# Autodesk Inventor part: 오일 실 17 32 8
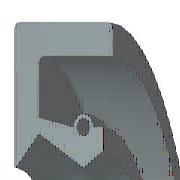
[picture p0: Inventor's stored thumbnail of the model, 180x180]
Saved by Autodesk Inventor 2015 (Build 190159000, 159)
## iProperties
IsCustomPart: 1
Created: 2012-02
Part Number: 오일 실 17 32 8
Material: 고무
Description: 오일-실
Document SubType Name: Modeling
Standard: KS B 2804
Designer: mduedu
Standards Organization: KS
Language: ko-KR
Size Designation: D - 17 32 8
Categories: <MemberInstance><Categories><Category DisplayName="샤프트 부품" InternalName="7f7aeb1f-a693-4053-b835-cee3144e0d98" Mnemonic="SHFT"><Category DisplayName="실링" Intern
Density: 0.93 g/cm^3
Appearance: 고무 - 검은색 - 버전 1.1
Author: mduedu
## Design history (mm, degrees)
revolve "본체" stored, may be unused: angle "d17" = 90 deg
revolve "스프링1" stored, may be unused: angle "d18" = 90 deg
body "Solid1"
sketch "스케치1"
  geometry: L1 (0, 16)-(8, 16); L2 (8, 14.25)-(1.75, 14.25); L3 (1.75, 10.25)-(4.9, 8.5); L4 (4.9, 8.5)-(0, 8.5); L5 (0, 0)-(9.586, 0) reference; L6 (4.9, 8.5)-(6.3, 9.375); L7 (0, 18)-(0, -3) reference; L8 (-1.941, 0)-(11.507, 0) reference; L9 (4.2, 10.6)-(1.75, 11.21); L10 (1.75, 11.21)-(1.75, 14.25); L11 (0, 16)-(0, 8.588); L12 (4.9, 8.5)-(0, 8.5); L13 (1.75, 10.25)-(0.152, 8.528); L14 (8, 16)-(8, 14.25); L15 (5.6, 10.6)-(6.3, 10.6); L16 (6.3, 10.6)-(6.3, 9.375); C1 r 0.455 at (4.9, 10.6); A1 r 0.7 centre (4.9, 10.6) between (5.6, 10.6) and (4.2, 10.6); A2 r 0.088 centre (0.088, 8.588) between (0, 8.588) and (0.152, 8.528); 1 further point
  constraints: 28 end point, 5 horizontal alignment, 5 point on line, 4 point on circle, 4 vertical alignment, 3 centre point, 3 tangent, 2 collinear, 2 horizontal, 2 perpendicular, 1 coincident, 1 parallel
  dimensions: "d0" = 32 diameter of L1 L5 (= SD2); "d1" = 1.75 distance of L1.end L2.start (= SD); "d2" = 0.91 diameter of C1 (= SPDI); "d3" = 1.4 diameter of A1 (= SPDA); "d4" = 17 diameter of L3.end L5 (= NND); "d5" = 20.5 diameter of L3.start L5 (= TKDM); "d7" = 22.42 diameter of L9.end L5 (= TKDM + 0.24 x SWDT); "d8" = 1.75 distance between parallel lines of L11 L10 (= SD); "d9" = 4.9 distance from line of L11 C1.centre (= SPDST); "d10" = 21.2 diameter of C1.centre L5 (= HLDM); "d11" = 0.0875 radius of A2 (= 0.25 x LAB); "d12" = 6.3 distance between parallel lines of L11 L16 (= SDI); "d13" = 18.75 diameter of L6.end L5 (= ABDM); "d14" = 8 distance from line of L11 L1.end (= SWDT)
fillet "모깎기1" dims "d6" = 0.3 (= RR)
other parameters: "SD2" = 32 [user parameter; used in 1 equation term], "SWDT" = 8 [user parameter; used in 2 equation terms], "RR" = 0.3 [user parameter; used in 1 equation term], "SD" = 1.75 [user parameter; used in 2 equation terms], "NND" = 17 [user parameter; used in 1 equation term], "SPDA" = 1.4 [user parameter; used in 1 equation term], "SPDI" = 0.91 [user parameter; used in 1 equation term], "TKDM" = 20.5 [user parameter; used in 2 equation terms], "HLDM" = 21.2 [user parameter; used in 1 equation term], "ABDM" = 18.75 [user parameter; used in 1 equation term], "SDI" = 6.3 [user parameter; used in 1 equation term], "SPDST" = 4.9 [user parameter; used in 1 equation term], "LAB" = 0.35 [user parameter; used in 1 equation term], "d15" = 0, "d16" = 0, "d19" = 0
